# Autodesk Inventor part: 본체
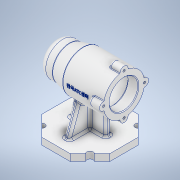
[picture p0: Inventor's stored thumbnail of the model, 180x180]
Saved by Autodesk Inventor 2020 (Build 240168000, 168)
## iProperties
Created: 2021-01
Part Number: 본체
Material: 알루미늄 6061
Document SubType Name: Modeling
Designer: PC2-13
Density: 2.7 g/cm^3
Appearance: 알루미늄 - 평지
Mass: 629.797 g
Surface Area: 614.224 cm^2
Volume: 233.258 cm^3
Author: PC2-13
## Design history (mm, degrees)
sketch "스케치1"
  geometry: L1 (-50, 50)-(50, 50); L2 (50, 50)-(50, -50); L3 (50, -50)-(-50, -50); L4 (-50, -50)-(-50, 50); L5 (-50, 50)-(50, -50); L6 (50, 50)-(-50, -50); 1 further point
  constraints: 12 end point, 2 midpoint, 2 parallel, 1 horizontal, 1 perpendicular
  dimensions: "d0" = 100 distance of L2.end L3.end; "d1" = 100 distance of L1.end L2.end
extrude "돌출1" new body sketch "스케치1" distance "d2" = 10; taper "d3" = 0 deg
sketch "스케치2"
  geometry: L1 (50, 75)-(-50, 75); L2 (50, 75)-(50, 90); L3 (40, 100)-(30, 100); L4 (-50, 75)-(-50, 105); L5 (-50, 105)-(10, 105); L6 (10, 105)-(30, 100); L7 (-50, 96)-(-35, 96); L8 (-35, 96)-(-35, 99); L9 (-35, 99)-(7, 99); L10 (7, 99)-(7, 96); L11 (7, 96)-(19, 96); L12 (19, 96)-(19, 92.5); L13 (19, 92.5)-(37, 92.5); L14 (37, 92.5)-(37, 91); L15 (37, 91)-(41, 91); L16 (41, 91)-(41, 85.5); L17 (41, 85.5)-(44, 85.5); L18 (44, 85.5)-(44, 75); A1 r 10 centre (40, 90) between (50, 90) and (40, 100); 3 further points
  constraints: 36 end point, 9 perpendicular, 5 vertical, 4 point on line, 2 horizontal, 2 point on circle, 2 tangent, 1 centre point, 1 midpoint, 1 parallel, 1 vertical alignment
  dimensions: "d4" = 100 distance of L1.start L1.end; "d5" = 75 distance from line of point (0, 0) L1; "d6" = 25 distance of L1.start point (50, 100); "d7" = 20 distance of point (50, 100) L3.end; "d8" = 30 distance of L1.end L4.end; "d9" = 60 distance of L4.end L5.end; "d10" = 10 radius of A1; "d11" = 15 distance of L7.start L7.end; "d12" = 42 diameter of L7 L1; "d13" = 42 distance of L8.end L9.end; "d14" = 48 diameter of L9 L1; "d15" = 12 distance of L10.end L11.end; "d16" = 42 diameter of L11 L1; "d17" = 18 distance of L12.end L13.end; "d18" = 35 diameter of L13 L1; "d19" = 4 distance of L14.end L15.end; "d20" = 32 diameter of L15 L1; "d21" = 3 distance of L16.end L17.end; "d22" = 21 diameter of L17 L1
revolve "회전1" sketch "스케치2" stored, may be unused: angle "d23" = 90 deg
fillet "모깎기1" dims "d24" = 3
chamfer "모따기1" distance "d25" = 1; stored, may be unused: second distance "d26" = 2, angle "d27" = 45 deg
fillet "모깎기2" dims "d28" = 0.3
fillet "모깎기3" dims "d29" = 3
fillet "모깎기4" dims "d30" = 3
sketch "스케치3"
  geometry: A1 r 30 centre (0, 0) between (-29.4, -5.97) and (-29.4, 5.97) reference; A2 r 6 centre (-30, 0) between (-29.4, 5.97) and (-29.4, -5.97); 1 further point
  constraints: 4 point on circle, 1 centre point, 1 horizontal alignment
  dimensions: "d32" = 12 diameter of A2; "d33" = 30 distance of A1.centre A2.centre
extrude "돌출2" join sketch "스케치3" distance "d34" = 16; taper "d35" = 0 deg
fillet "모깎기5" dims "d36" = 3
fillet "모깎기6" dims "d37" = 1
sketch "스케치4"
  geometry: A1 r 6 centre (0, 0) between (-0.171, 5.998) and (-0.171, -5.998) reference; 2 further points
  constraints: 1 coincident
hole "구멍1" sketch "스케치4" at (0, 0) diameter "d38" = 3.242; stored, may be unused: countersink angle "d42" = 90 deg, drill point angle "d44" = 118 deg; dims "d39" = 8, "d40" = 4, "d41" = 2, "d43" = 10
sketch "스케치5"
  geometry: L1 (-50, 10)-(50, 10) reference; L2 (-35, 10)-(-19.606, 52.293); L3 (-50, 0)-(-50, 10) reference; L4 (35, 10)-(19.606, 52.293); L5 (50, 0)-(50, 10) reference; L6 (-35, 10)-(35, 10); L7 (-35, 10)-(35, 10); A1 r 30 centre (0, 75) between (-29.226, 68.229) and (-6.771, 45.774) reference; A2 r 30 centre (0, 75) between (6.771, 45.774) and (29.226, 68.229) reference; A3 r 30 centre (0, 75) between (-19.606, 52.293) and (19.606, 52.293); 3 further points
  constraints: 8 end point, 4 point on circle, 2 collinear, 2 point on line, 1 centre point, 1 coincident, 1 concentric
  dimensions: "d48" = 15 distance from line of L3 L2.start; "d49" = 110 deg angle of L2 L1; "d50" = 15 distance from line of L5 L4.start; "d51" = 110 deg angle of L4 L1
extrude "돌출3" join sketch "스케치5" stored distance "d52" = 8; taper "d53" = 0 deg
sketch "스케치7"
  geometry: L1 (-50, 10)-(50, 10) reference; L2 (27, 10)-(23.741, 26.766); 1 further point
  constraints: 2 end point, 1 point on line
  dimensions: "d57" = 23 distance of L2.start L1.end; "d58" = 101 deg angle of L2 L1
feature "리브1" sketch "스케치7" dims "d59" = 1, "d60" = 8, "d61" = 0, "d62" = 0, "d63" = 1, "d64" = 1
sketch "스케치9"
  geometry: L1 (0, 4)-(27, 4); L2 (27, 4)-(27, -4); L3 (27, -4)-(0, -4); L4 (0, -4)-(0, 4); L5 (50, -50)-(50, 50) reference; 2 further points
  constraints: 8 end point, 2 coincident, 2 parallel, 1 horizontal, 1 midpoint, 1 perpendicular
  dimensions: "d68" = 8 distance between parallel lines of L3 L1; "d69" = 23 distance between parallel lines of L5 L2
extrude "돌출6" join sketch "스케치9" stored distance "d70" = 8; taper "d71" = 0 deg
fillet "모깎기7" dims "d72" = 3
fillet "모깎기8" dims "d73" = 3
sketch "스케치10"
  geometry: L1 (-50, 50)-(-50, -50) reference; L2 (50, 50)-(-50, 50) reference; L3 (-50, 20.711)-(-20.711, 50); L4 (-20.711, 50)-(20.711, 50); L5 (20.711, 50)-(50, 20.711); L6 (50, 20.711)-(50, -20.711); L7 (50, -20.711)-(20.711, -50); L8 (20.711, -50)-(-20.711, -50); L9 (-20.711, -50)-(-50, -20.711); L10 (-50, -20.711)-(-50, 20.711); L11 (50, -50)-(-50, -50); L12 (-50, -50)-(-50, 50); L13 (-50, 50)-(50, 50); L14 (50, 50)-(50, -50); L15 (50, -50)-(-50, 50); L16 (-50, -50)-(50, 50); C1 r 50 at (0, 0); 13 further points
  constraints: 28 end point, 4 midpoint, 2 coincident, 2 parallel, 1 centre point, 1 horizontal, 1 perpendicular, 17 other
  dimensions: "d74" = 100 diameter of C1
sketch "스케치11"
  geometry: 1 further point
extrude "돌출7" cut sketch "스케치10" distance "d75" = 43; taper "d76" = 0 deg
sketch "스케치12" dims "d77" = 100
  geometry: L1 (-50, 20.711)-(-20.711, 50) reference; L2 (0, 0)-(-35.355, 35.355); L3 (0, 0)-(0, 50); C1 r 4.5 at (-35.355, 35.355); 1 further point
  constraints: 4 end point, 1 centre point, 1 coincident, 1 midpoint, 1 vertical, 1 vertical alignment, 2 other
  dimensions: "d78" = 9 diameter of C1; "d79" = 45 deg angle of L3 L2 (derived)
extrude "돌출8" cut sketch "스케치12" distance "d80" = 43; taper "d81" = 0 deg
node "작업 평면1"
sketch "스케치13"
  geometry: L1 (50, 105.171)-(50, 111) reference; L2 (50, 69.002)-(50, 80.998) reference; 3 further points
  constraints: 1 horizontal alignment, 1 midpoint, 1 other
  dimensions: "d86" = 38 distance from line of point (12, 75) L1
feature "엠보싱1" sketch "스케치13" dims "d0" = 100, "d1" = 100, "d87" = 0.5, "d88" = 0
node "솔리드1"
pattern_circular "원형 패턴1" dims "d46" = 360 deg
pattern_circular "원형 패턴2" dims angle "d83" = 360 deg
other parameters: "d85" = -74.5
